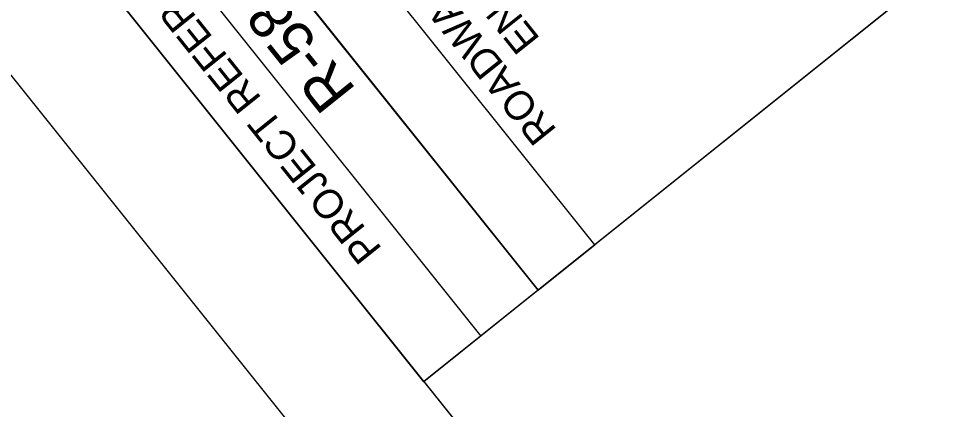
# Model space of a CAD drawing. Extents: x 473437 to 475344, y 504319 to 506318.
# Drawn here: x 473521.1 to 473682.6, y 505473.2 to 505540.2 of the extents above; entities that cross this region are included whole.
import ezdxf

# ---------------------------------------------------------------- set-up
doc = ezdxf.new("R2010")
doc.units = 0
for name, color, linetype in [('Sheet Clip Boundary CELL', 7, 'Continuous'), ('Sheet Data Field CELL', 7, 'Continuous'), ('Sheet Plan CELL', 7, 'Continuous'), ('Sheet Plot Border Outside CELL', 7, 'Continuous')]:
    doc.layers.add(name, color=color, linetype=linetype)

msp = doc.modelspace()

# ---------------------------------------------------------------- linework, layer by layer
at = {"layer": 'Sheet Clip Boundary CELL'}
msp.add_lwpolyline([(473726.06, 505586.42), (473590.56, 505477.98), (474216.19, 504696.26), (474256.15, 504661.57), (474721.23, 504717.86), (474850.21, 504821.06), (475222.63, 505119.12), (474407.1, 506139.11), (474332.49, 506089.63), (474296.32, 506065.24), (474178.01, 505990.66), (474151.65, 505998.17), (473818.14, 505733.37), (473690.29, 505631.86)], close=True, dxfattribs=at)
at = {"layer": 'Sheet Plan CELL'}
for p, q in [((473610.14, 505493.63), (473485.13, 505649.8)), ((473610.14, 505493.63), (473485.13, 505649.8)), ((473600.36, 505485.79), (473475.37, 505641.99)), ((473610.14, 505493.63), (473619.89, 505501.44))]:
    msp.add_line(p, q, dxfattribs=at)
for points in [[(473465.55, 505634.17), (474402.85, 504463.03), (475222.63, 505119.12), (474285.35, 506290.25)], [(473590.56, 505477.96), (473465.55, 505634.17), (473485.13, 505649.8), (473610.14, 505493.63)], [(473619.89, 505501.44), (473557.38, 505579.55), (473645.22, 505649.85), (473707.71, 505571.73)]]:
    msp.add_lwpolyline(points, close=True, dxfattribs=at)
at = {"layer": 'Sheet Plot Border Outside CELL'}
msp.add_lwpolyline([(475344.24, 505003.2), (474292.3, 506317.59), (473437.39, 505633.37), (474489.32, 504318.99)], close=True, dxfattribs=at)

# ---------------------------------------------------------------- texts
at = {"layer": 'Sheet Data Field CELL'}
msp.add_text('R-5861', height=7.5, rotation=128.6712, dxfattribs=at).set_placement((473579.08, 505528.03))
at = {"layer": 'Sheet Plan CELL'}
for s, height, p in [('PROJECT REFERENCE NO.', 5.0001, (473583.5, 505500.74)), ('ROADWAY DESIGN', 5.0001, (473613.49, 505521.12)), ('ENGINEER', 5, (473610.63, 505536.76))]:
    msp.add_text(s, height=height, rotation=128.6712, dxfattribs=at).set_placement(p)

doc.saveas('drawing.dxf')
